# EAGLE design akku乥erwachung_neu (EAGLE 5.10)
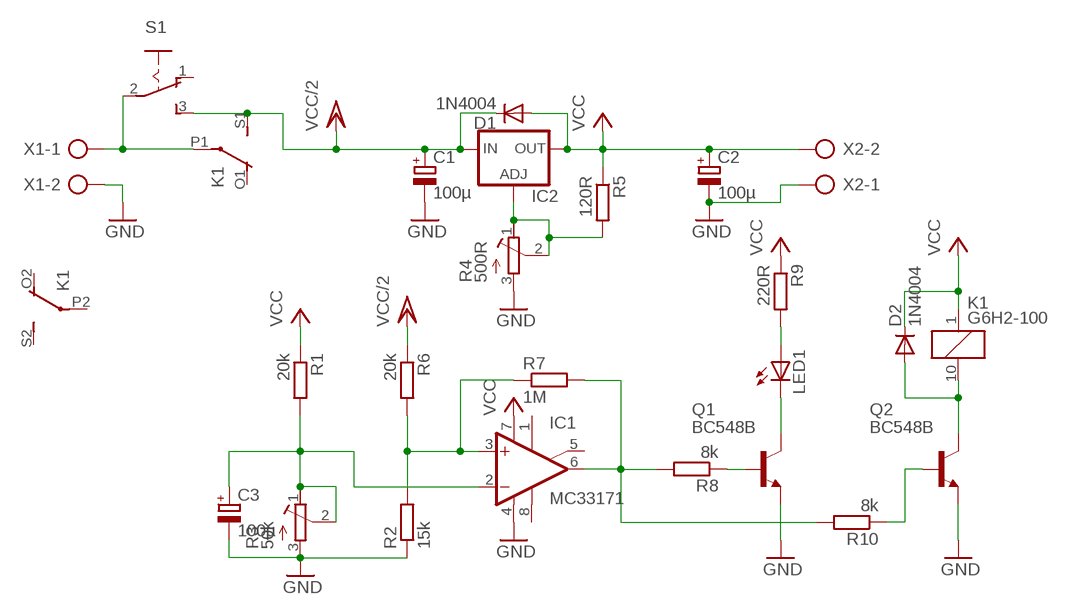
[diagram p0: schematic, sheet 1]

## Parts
C1  100µ  CPOL-EUE2.5-6  [E2,5-6]
C2  100µ  CPOL-EUE2.5-6  [E2,5-6]
C3  100µ  CPOL-EUE2.5-6  [E2,5-6]
D1  1N4004  [DO41-10]
D2  1N4004  [DO41-10]
IC1  TL071P  [DIL08]
IC2  LM317TS  [317TS]
K1  G6H2-100  [G6H2-100]
LED1  LED5MM  [LED5MM]
Q1  BC548B  [TO92-EBC]
Q2  BC548B  [TO92-EBC]
R1  20k  R-EU_0309/12  [0309/12]
R2  15k  R-EU_0309/12  [0309/12]
R3  50k  R-TRIMM43P  [RTRIM43P]
R4  500R  R-TRIMM43P  [RTRIM43P]
R5  120R  R-EU_0309/12  [0309/12]
R6  20k  R-EU_0309/12  [0309/12]
R7  1M  R-EU_0309/12  [0309/12]
R8  8k  R-EU_0309/12  [0309/12]
R9  220R  R-EU_0309/12  [0309/12]
R10  8k  R-EU_0309/12  [0309/12]
S1  255SB  [255SB]
X1  AK500/2  [AK500/2]
X2  AK500/2  [AK500/2]

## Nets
GND: C1.- C2.- C3.- IC1.4(V-) Q1.E Q2.E R2.1 R3.3(E) R4.3(E) X1.2 X2.1
N$1: Q1.B R8.1
N$2: IC2.1(ADJ) R4.1(A) R4.2(S) R5.2
N$3: C3.+ IC1.2(-IN) R1.2 R3.1(A) R3.2(S)
N$4: IC1.3(+IN) R2.2 R6.2 R7.1
N$5: LED1.A R9.2
N$7: IC1.6(OUT) R7.2 R8.2 R10.2
N$8: K1.P1(2:P) S1.2(P) X1.1
N$9: LED1.K(C) Q1.C
N$10: D2.A K1.10 Q2.C
N$11: Q2.B R10.1
VCC: C2.+ D1.A D2.C IC1.7(V+) IC2.2(OUT) K1.1 R1.1 R5.1 R9.1 X2.2
VCC/2: C1.+ D1.C IC2.3(IN) K1.S1(2:S) R6.1 S1.3(S)
Unconnected: IC1.1(ON1) IC1.5(ON2) IC1.8(OPT) K1.O1(2:O) K1.O2(3:O) K1.P2(3:P) K1.S2(3:S) S1.1(O)

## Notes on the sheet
- MC33171

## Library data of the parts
C1-C3 = rcl:CPOL-EU: POLARIZED CAPACITOR, European symbol
D1 D2 = diode:1N4004: DIODE
IC1 = linear:TL071: OP AMP
IC2 = v-reg:LM317TS: VOLTAGE REGULATOR
K1 = relay:G6H2-100: RELAY 2 x switch, 0.5 A/125 V AC, 1 A/30 V DC, Omron
LED1 = led:LED: LED
Q1 Q2 = transistor-npn:BC548*: NPN Transistor
R1 R2 R5-R10 = resistor:R-EU_: RESISTOR, European symbol
R3 R4 = rcl:R-TRIMM: Trimm resistor
S1 = switch:255SB: SLIDING SWITCH Distributor Buerklin, 11G810
X1 X2 = con-ptr500:AK500/2: CONNECTOR

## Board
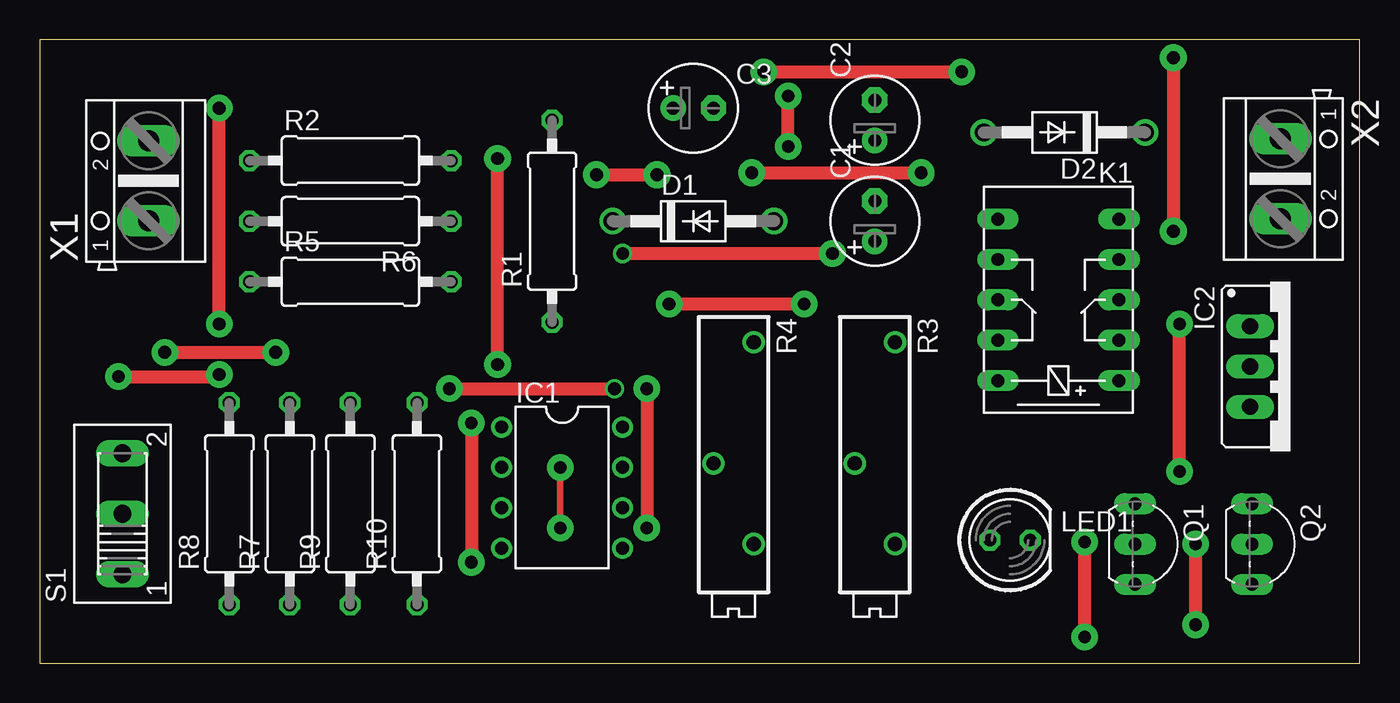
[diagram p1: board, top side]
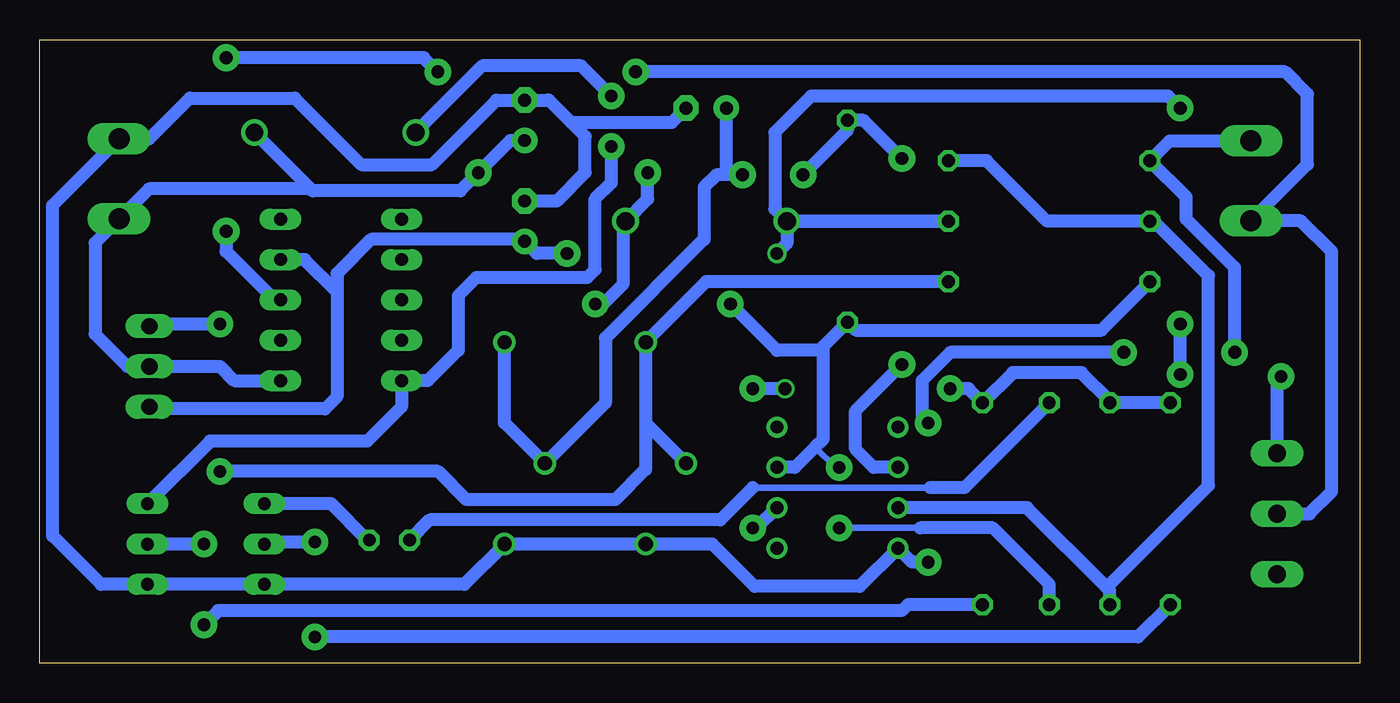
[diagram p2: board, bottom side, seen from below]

Size 83.11 x 39.23 mm. Coordinates in mm from the lower left corner, seen from the top.
Outline: 0,0 83.11,0 83.11,39.23 0,39.23 0,0
Copper layers (1*16): Top 0.035mm / dielectric 1.5mm / Bottom 0.035mm
Design rules "default": minimum track width 10mil, minimum drill 24mil, track to track 8mil, track to pad 8mil, pad to pad 8mil, via to via 8mil, smd to smd 8mil, copper to edge 40mil, drill to drill 8mil, minimum pad ring 10mil, minimum via ring 8mil, stop-mask expansion 4mil, vias tented up to drill 0mil, thermal gap 10mil

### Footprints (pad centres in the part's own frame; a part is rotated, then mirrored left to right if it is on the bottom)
E2,5-6 = drill 0.813 pad 1.6 round: + -1.27,0 | drill 0.813 pad 1.6 octagon: - 1.27,0
DO41-10 = drill 1.118 round: A 5.08,0; C -5.08,0
DIL08 = drill 0.813 pad 1.27 round: 1 -3.81,-3.81; 2 -1.27,-3.81; 3 1.27,-3.81; 4 3.81,-3.81; 5 3.81,3.81; 6 1.27,3.81; 7 -1.27,3.81; 8 -3.81,3.81
317TS = drill 1.016 long: 1 -2.54,-2.54; 2 0,-2.54; 3 2.54,-2.54
G6H2-100 = drill 0.813 long: 1 -5.08,-3.81; 5 5.08,-3.81; 6 5.08,3.81; 10 -5.08,3.81; O1 -2.54,-3.81; O2 -2.54,3.81; P1 0,-3.81; P2 0,3.81; S1 2.54,-3.81; S2 2.54,3.81
LED5MM = drill 0.813 octagon: A -1.27,0; K 1.27,0
TO92-EBC = drill 0.813 long: B 0,-1.27; C -2.54,-1.27; E 2.54,-1.27
0309/12 = drill 0.813 octagon: 1 -6.35,0; 2 6.35,0
RTRIM43P = drill 0.9 round: 1 -7.62,1.27; 2 0,-1.27; 3 5.08,1.27
255SB = drill 1.118 long: 1 -3.81,0; 2 0,0; 3 3.81,0
AK500/2 = drill 1.321 long: 1 -2.515,0; 2 2.515,0

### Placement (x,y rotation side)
C1  52.58,27.81 90 top
C2  52.58,34.16 90 top
C3  41.15,34.92 0 top
D1  41.15,27.81 0 top
D2  64.52,33.4 180 top
IC1  32.89,11.05 270 top
IC2  78.74,18.67 270 top
K1  64.14,22.86 90 top
LED1  61.09,7.75 0 top
Q1  70.23,7.49 270 top
Q2  77.6,7.49 270 top
R1  32.26,27.81 90 top
R2  19.56,31.62 0 top
R3  52.58,12.57 270 top
R4  43.69,12.57 270 top
R5  19.56,24 0 top
R6  19.56,27.81 180 top
R7  15.75,10.03 90 top
R8  11.94,10.03 90 top
R9  19.56,10.03 90 top
R10  23.75,10.03 90 top
S1  5.21,9.4 90 top
X1  6.86,30.35 90 top
X2  78.1,30.48 270 top

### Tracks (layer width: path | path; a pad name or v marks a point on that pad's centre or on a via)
GND  (via drill 0.8 pad 1.68)
  Top 0.813: v27.18,15.11 v27.18,6.35 | v7.87,19.56 v14.86,19.56
  Bottom 0.406: 48.77,30.86 48.77,33.02 51.18,35.43
  Bottom 0.813: X1.2 11.96,32.87 R2.1 10.92,29.34 10.92,27.94 7.87,24.89 v7.87,19.56 | 49.66,34.04 51.05,35.43 51.18,35.43 C2.- 54.36,35.43 58.42,31.37 62.87,31.37 67.06,35.56 73.66,35.56 76.22,32.99 X2.1 82.3,28.8 82.3,8 79.25,4.95 Q2.E Q1.E 56.39,4.95 R3.3 R4.3 40.77,7.49 38.1,4.83 31.5,4.83 IC1.4 28.19,6.35 v27.18,6.35 | 49.66,34.04 48.77,33.15 48.77,30.86 50.55,29.08 C1.- | v27.18,15.11 27.56,15.49 27.56,17.78 25.78,19.56 v14.86,19.56 | C3.- 43.31,34.04 49.66,34.04
N$1  (via drill 0.8 pad 1.68)
  Top 0.813: v65.79,1.65 v65.79,7.62
  Bottom 0.813: Q1.B 68.83,7.62 v65.79,7.62 | v65.79,1.65 13.97,1.65 R8.1
N$2  (via drill 0.8 pad 1.68)
  Top 0.813: v71.75,12.06 v71.75,21.34
  Bottom 0.813: 44.96,15.11 R4.1 41.15,24 R5.2 | 44.96,15.11 R4.2 | IC2.1 76.07,21.34 v71.75,21.34 | v71.75,12.06 58.04,12.06 56.26,10.29 46.86,10.29 44.96,12.19 44.96,15.11
N$3  (via drill 0.8 pad 1.68)
  Top 0.813: v28.83,18.8 v28.83,31.75 | v35.05,30.73 v38.86,30.73
  Bottom 0.813: R3.1 53.85,15.11 R3.2 47.5,16.38 47.5,20.45 41.28,26.67 41.28,29.97 40.51,30.73 39.5,30.73 | v28.83,31.75 31.24,34.16 R1.2 32.26,33.53 v35.05,30.73 | v28.83,18.8 31.75,15.88 31.75,13.46 30.61,12.32 IC1.2 | v38.86,30.73 39.5,30.73 | C3.+ 39.88,31.12 39.5,30.73
N$4
  Bottom 0.813: R2.2 23.49,31.62 19.68,27.81 R6.2 12.95,27.81 9.52,24.38 9.52,11.18 15.94,4.76 | IC1.3 20.95,9.78 15.94,4.76 | 15.94,4.76 15.75,4.57 R7.1
N$5
  Bottom 0.406: 27.05,11.05 38.23,11.05
  Bottom 0.813: LED1.A 58.55,9.02 40.26,9.02 38.23,11.05 | R9.2 24.89,11.05 27.05,11.05
N$7  (via drill 0.8, 0.8 pad 1.68)
  Top 0.813: v38.23,17.27 v38.23,8.51 | v25.78,17.27 v36.2,17.27
  Bottom 0.813: R8.2 R7.2 15.75,16.51 17.53,18.29 21.84,18.29 R10.2 24.64,17.27 v25.78,17.27 | IC1.6 37.97,8.51 v38.23,8.51 | v36.2,17.27 v38.23,17.27
N$8  (via drill 0.8 pad 1.68)
  Top 0.813: v45.59,37.21 v58.04,37.21 | v71.37,38.1 v71.37,27.18
  Bottom 0.813: S1.2 3.17,9.4 1.78,10.79 1.78,25.91 3.71,27.84 X1.1 3.3,31.39 3.3,35.81 4.7,37.21 v45.59,37.21 | v58.04,37.21 58.93,38.1 v71.37,38.1 | v71.37,27.18 71.37,25.91 68.33,22.86 K1.P1
N$9
  Bottom 0.813: Q1.C 64.77,10.03 62.48,7.75 LED1.K
N$10  (via drill 0.8 pad 1.68)
  Top 0.813: v47.12,32.51 v47.12,35.69
  Bottom 0.813: K1.10 60.2,17.65 | D2.A 55.25,37.59 49.02,37.59 v47.12,35.69 | K1.10 58.67,17.78 56.77,19.68 56.77,23.11 55.63,24.26 48.64,24.26 48.13,24.76 48.13,29.21 47.12,30.23 v47.12,32.51 | Q2.C 72.39,13.97 62.48,13.97 60.33,16.13 K1.10
N$11  (via drill 0.8 pad 1.68)
  Top 0.813: v72.77,2.41 v72.77,7.49
  Bottom 0.813: v72.77,7.49 Q2.B | v72.77,2.41 71.88,3.3 28.83,3.3 28.45,3.68 R10.1
VCC  (via drill 0.8 pad 1.68)
  Top 0.406: v32.77,8.51 v32.77,12.32
  Top 0.813: v44.83,30.86 v55.5,30.86 | v39.62,22.61 v48.13,22.61
  Bottom 0.406: 27.69,8.51 v32.77,8.51 | v32.77,12.32 33.02,12.32 34.29,13.59
  Bottom 0.813: K1.1 70.87,17.78 71.75,18.67 IC2.2 77.6,18.67 79.63,20.7 79.63,26.44 X2.2 76.22,29.84 66.04,29.84 | 66.04,29.84 65.91,29.72 56.64,29.72 v55.5,30.86 53.47,32.89 C2.+ | 66.04,29.84 D2.C | v44.83,30.86 44.83,29.21 D1.A 46.36,27.69 46.36,23.88 47.62,22.61 v48.13,22.61 | R5.1 16.26,20.95 31.75,20.95 R1.1 33.78,19.94 33.78,19.68 | 33.78,19.68 33.78,14.1 34.29,13.59 35.56,12.32 IC1.7 | v39.62,22.61 36.7,19.68 33.78,19.68 | R9.1 19.56,4.95 23.11,8.51 27.69,8.51
VCC/2  (via drill 0.8, 0.8 pad 1.68)
  Top 0.813: v36.7,25.78 v49.91,25.78 | v11.3,21.34 v11.3,34.92 | v11.3,18.16 11.18,18.03 v4.95,18.03
  Bottom 0.813: K1.S1 66.42,25.4 64.39,23.37 | 64.39,23.37 64.39,16.76 65.15,16 76.07,16 IC2.3 | 64.39,23.37 64.39,24.51 62.23,26.67 52.71,26.67 C1.+ 51.82,25.78 v49.91,25.78 | D1.C R6.1 35.81,27.81 35.94,27.69 | v36.7,25.78 36.07,26.42 D1.C | v11.3,18.16 v11.3,21.34 | v4.95,18.03 5.21,17.78 S1.3 | v11.3,34.92 12.07,35.69 34.54,35.69 36.83,33.4 36.83,28.57 D1.C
